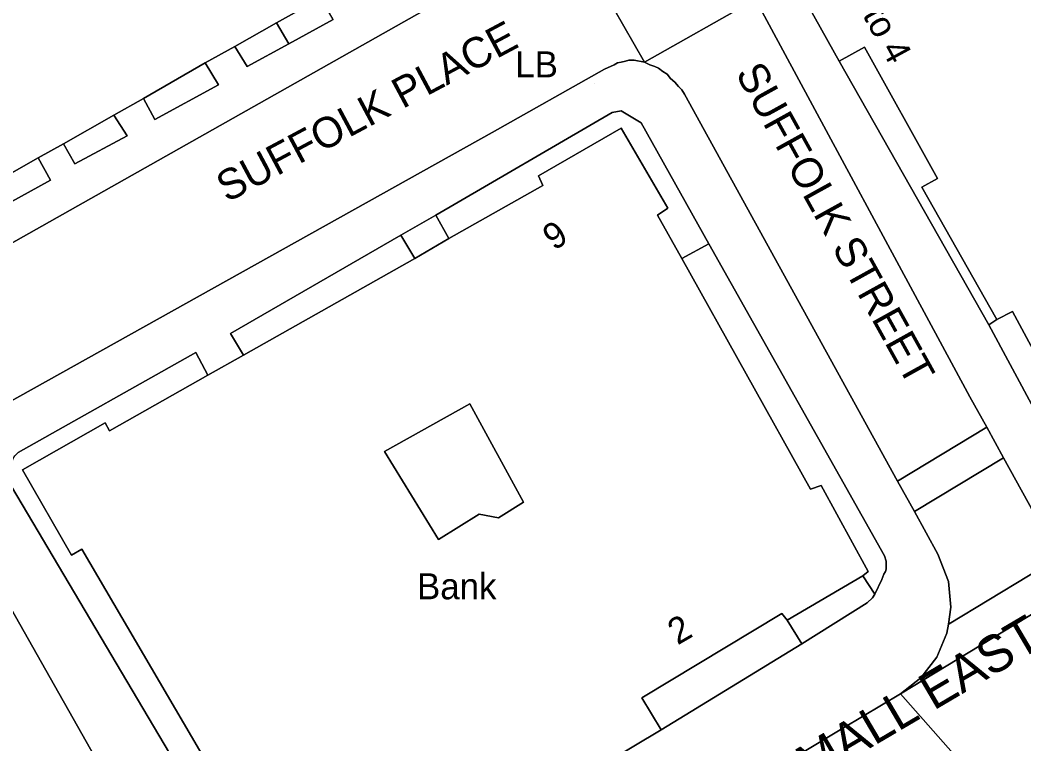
# Model space of a CAD drawing. Extents: x 529240 to 530363, y 179600 to 180767.
# Drawn here: x 529791.2 to 529848.9, y 180434.3 to 180475.9 of the extents above; entities that cross this region are included whole.
import ezdxf

# ---------------------------------------------------------------- set-up
doc = ezdxf.new("R2010")
doc.units = 0
for name, color, linetype in [('Building', 7, 'Continuous'), ('General surface', 7, 'Continuous'), ('Road Or Track', 7, 'Continuous'), ('Roadside', 7, 'Continuous'), ('Structure', 7, 'Continuous'), ('Unclassified', 7, 'Continuous')]:
    doc.layers.add(name, color=color, linetype=linetype)

msp = doc.modelspace()

# ---------------------------------------------------------------- linework, layer by layer
at = {"layer": 'Building'}
for points in [[(529786.55, 180464.75), (529792.25, 180468), (529793.7, 180468.8), (529796.6, 180470.45), (529798.3, 180471.4), (529801.85, 180473.45), (529803.55, 180474.4), (529805.95, 180475.75), (529808.5, 180477.2), (529810.3, 180478.25), (529818.45, 180482.85), (529815.15, 180488.6), (529810.7, 180486.15), (529807.1, 180484.1), (529806.15, 180485.75), (529804.1, 180484.5), (529802, 180483.3), (529799.8, 180487.05), (529800.55, 180487.5), (529798.55, 180490.95), (529797.45, 180492.85), (529794.4, 180498.1), (529771.3, 180485.1), (529783.65, 180463.1)], [(529847.35, 180458.7), (529843.05, 180466.3), (529843.95, 180466.8), (529839.75, 180474.35), (529838.3, 180473.55), (529846.9, 180458.4)], [(529812.15, 180451.1), (529817.05, 180453.85), (529820.15, 180448.2), (529818.7, 180447.3), (529817.6, 180447.5), (529815.25, 180446.05)], [(529835.3, 180441.4), (529836.15, 180440.05), (529839.9, 180442.4), (529840.2, 180442.7), (529840.35, 180442.9), (529839.65, 180443.95)]]:
    msp.add_lwpolyline(points, close=True, dxfattribs=at)
for points in [[(529851.4, 180488.55), (529847.75, 180486.4), (529844.7, 180491.5), (529840.9, 180497.9), (529829.65, 180492.1), (529836.55, 180479.75), (529835.2, 180479.1), (529838.3, 180473.55), (529839.75, 180474.35), (529843.95, 180466.8), (529843.05, 180466.3), (529847.35, 180458.7), (529848.25, 180459.15), (529852.1, 180452)], [(529835.2, 180479.1), (529838.3, 180473.55)], [(529805.95, 180475.75), (529808.5, 180477.2)], [(529803.55, 180474.4), (529805.95, 180475.75)], [(529801.85, 180473.45), (529803.55, 180474.4)], [(529847.35, 180458.7), (529843.05, 180466.3), (529843.95, 180466.8), (529839.75, 180474.35), (529838.3, 180473.55)], [(529798.3, 180471.4), (529801.85, 180473.45)], [(529796.6, 180470.45), (529798.3, 180471.4)], [(529793.7, 180468.8), (529796.6, 180470.45)], [(529820, 180430.3), (529828.05, 180435.1), (529826.95, 180436.95), (529835, 180441.8), (529835.3, 180441.4), (529839.65, 180443.95), (529839.95, 180444.2), (529837.25, 180449.15), (529836.65, 180448.95), (529829.25, 180462.2), (529827.85, 180464.7), (529828.45, 180465.1), (529825.75, 180469.7), (529821, 180466.95), (529821.25, 180466.4), (529815.85, 180463.35), (529813.9, 180462.2), (529804.05, 180456.65), (529802, 180455.5), (529796.35, 180452.3), (529796.1, 180452.75), (529791.35, 180450.05), (529794.15, 180445.15), (529794.75, 180445.5), (529804.15, 180429.45)], [(529815.85, 180463.35), (529821.25, 180466.4), (529821, 180466.95), (529825.75, 180469.7), (529828.45, 180465.1), (529827.85, 180464.7), (529829.25, 180462.2)], [(529792.25, 180468), (529793.7, 180468.8)], [(529786.55, 180464.75), (529792.25, 180468)], [(529847.35, 180458.7), (529848.25, 180459.15), (529852.1, 180452), (529867.28, 180461.19), (529874.9, 180465.8)], [(529813.9, 180462.2), (529815.85, 180463.35)], [(529804.05, 180456.65), (529813.9, 180462.2)], [(529829.25, 180462.2), (529836.65, 180448.95), (529837.25, 180449.15), (529839.95, 180444.2), (529839.65, 180443.95)], [(529802, 180455.5), (529804.05, 180456.65)], [(529820, 180430.3), (529819, 180432.05), (529810.85, 180427.15), (529811.1, 180426.65), (529806.65, 180423.95), (529803.55, 180429.05), (529804.15, 180429.45), (529794.75, 180445.5), (529794.15, 180445.15), (529791.35, 180450.05), (529796.1, 180452.75), (529796.35, 180452.3), (529802, 180455.5)], [(529812.15, 180451.1), (529815.25, 180446.05), (529817.6, 180447.5), (529818.7, 180447.3), (529820.15, 180448.2), (529817.05, 180453.85), (529812.15, 180451.1)], [(529839.65, 180443.95), (529835.3, 180441.4)], [(529839.65, 180443.95), (529840.35, 180442.9)], [(529835.3, 180441.4), (529835, 180441.8), (529826.95, 180436.95), (529828.05, 180435.1)], [(529828.05, 180435.1), (529820, 180430.3)]]:
    msp.add_lwpolyline(points, dxfattribs=at)
at = {"layer": 'General surface'}
for points in [[(529808.5, 180477.2), (529805.95, 180475.75), (529806.65, 180474.55), (529809.2, 180475.95)], [(529806.65, 180474.55), (529805.95, 180475.75), (529803.55, 180474.4), (529804.25, 180473.25)], [(529798.3, 180471.4), (529798.95, 180470.2), (529802.6, 180472.2), (529801.85, 180473.45)], [(529796.6, 180470.45), (529793.7, 180468.8), (529794.35, 180467.65), (529797.35, 180469.25)], [(529815.85, 180463.35), (529821.25, 180466.4), (529821, 180466.95), (529825.75, 180469.7), (529828.45, 180465.1), (529827.85, 180464.7), (529829.25, 180462.2), (529830.8, 180463.05), (529826.9, 180470), (529825.75, 180470.7), (529825.25, 180470.6), (529815.1, 180464.7)], [(529786.55, 180464.75), (529787.2, 180463.55), (529792.95, 180466.7), (529792.25, 180468)], [(529846.9, 180458.4), (529850.85, 180451.05), (529850.95, 180450.95), (529851.05, 180450.8), (529851.2, 180450.7), (529851.35, 180450.65), (529851.55, 180450.55), (529851.95, 180450.45), (529852.75, 180450.35), (529868.19, 180459.62), (529875.9, 180464.25), (529874.9, 180465.8), (529867.28, 180461.19), (529852.1, 180452), (529848.25, 180459.15), (529847.35, 180458.7)], [(529815.85, 180463.35), (529815.1, 180464.7), (529813.1, 180463.55), (529813.9, 180462.2)], [(529803.3, 180457.9), (529804.05, 180456.65), (529813.9, 180462.2), (529813.1, 180463.55)], [(529829.25, 180462.2), (529836.65, 180448.95), (529837.25, 180449.15), (529839.95, 180444.2), (529839.65, 180443.95), (529840.35, 180442.9), (529840.75, 180443.75), (529840.85, 180444.05), (529840.95, 180444.2), (529841, 180444.35), (529841, 180444.8), (529840.9, 180445.1), (529830.8, 180463.05)], [(529812.15, 180451.1), (529815.25, 180446.05), (529817.6, 180447.5), (529818.7, 180447.3), (529820.15, 180448.2), (529817.05, 180453.85)], [(529835.3, 180441.4), (529835, 180441.8), (529826.95, 180436.95), (529828.05, 180435.1), (529836.15, 180440.05)]]:
    msp.add_lwpolyline(points, close=True, dxfattribs=at)
msp.add_lwpolyline([(529790.7, 180449.1), (529805.8, 180423.6), (529805.95, 180423.45), (529806.5, 180423), (529806.6, 180422.95), (529806.7, 180422.85), (529807, 180422.7), (529807.25, 180422.7), (529807.45, 180422.8), (529820, 180430.3), (529819, 180432.05), (529810.85, 180427.15), (529811.1, 180426.65), (529806.65, 180423.95), (529803.55, 180429.05), (529804.15, 180429.45), (529794.75, 180445.5), (529794.15, 180445.15), (529791.35, 180450.05), (529796.1, 180452.75), (529796.35, 180452.3), (529802, 180455.5), (529801.3, 180456.8), (529791.1, 180451.05)], dxfattribs=at)
at = {"layer": 'Road Or Track'}
for points in [[(529827.1, 180473.5), (529833.48, 180477.11), (529828.83, 180485.42), (529822.35, 180481.8)], [(529827.1, 180473.5), (529827.4, 180473.35), (529827.7, 180473.25), (529827.9, 180473.15), (529828.15, 180472.95), (529828.4, 180472.8), (529828.6, 180472.55), (529828.85, 180472.35), (529829.05, 180472.1), (529829.25, 180471.9), (529829.4, 180471.65), (529841.65, 180449.4), (529846.78, 180452.5), (529845.81, 180454.25), (529833.48, 180477.11)], [(529847.74, 180450.75), (529846.78, 180452.5), (529841.65, 180449.4), (529842.62, 180447.65)], [(529847.74, 180450.75), (529842.62, 180447.65), (529843.96, 180445.21), (529844.57, 180443.63), (529844.71, 180442.15), (529844.57, 180441.18), (529844.61, 180441.2), (529851.45, 180445.33), (529851.1, 180445.58), (529850.59, 180445.95), (529849.86, 180446.9)], [(529841.82, 180437.17), (529855.04, 180445.19), (529853.89, 180444.86), (529852.7, 180444.88), (529851.56, 180445.25), (529851.45, 180445.33), (529844.61, 180441.2), (529844.57, 180441.18), (529844.49, 180440.67), (529843.9, 180439.29), (529842.99, 180438.1)], [(529855.04, 180445.19), (529841.82, 180437.17), (529846.15, 180432.27), (529846.48, 180432.34), (529846.74, 180432.2), (529846.85, 180431.64), (529852.12, 180431.04), (529853.55, 180433.47), (529856.1, 180436.61), (529858.54, 180438.84)], [(529813.74, 180420.91), (529819.63, 180415.23), (529819.86, 180415.75), (529839.31, 180427.98), (529841.93, 180429.63), (529846.13, 180432.27), (529846.15, 180432.27), (529841.82, 180437.17), (529838.54, 180435.21), (529835.89, 180433.62), (529819.89, 180424.05)]]:
    msp.add_lwpolyline(points, close=True, dxfattribs=at)
for points in [[(529821, 180480.2), (529784.7, 180459.7), (529783.31, 180458.62), (529782.36, 180458.26), (529782.17, 180458.23), (529785.79, 180450.85), (529786.04, 180451.39), (529786.72, 180452), (529788.7, 180452.9), (529818.35, 180469.45), (529824.8, 180473.1), (529825.35, 180473.35), (529825.55, 180473.45), (529825.75, 180473.5), (529826, 180473.55), (529826.2, 180473.6), (529826.5, 180473.6), (529827.1, 180473.5), (529822.35, 180481.8)], [(529822.35, 180481.8), (529822.2, 180481.6), (529822.1, 180481.4), (529821.9, 180481.1), (529821.7, 180480.75), (529821.6, 180480.6), (529821.4, 180480.45), (529821.2, 180480.35), (529821, 180480.2), (529784.7, 180459.7)], [(529845.81, 180454.25), (529833.48, 180477.11)], [(529827.1, 180473.5), (529826.5, 180473.6), (529826.2, 180473.6), (529826, 180473.55), (529825.75, 180473.5), (529825.55, 180473.45), (529825.35, 180473.35), (529824.8, 180473.1), (529818.35, 180469.45), (529788.7, 180452.9)], [(529841.65, 180449.4), (529829.4, 180471.65), (529829.25, 180471.9), (529829.05, 180472.1), (529828.85, 180472.35), (529828.6, 180472.55), (529828.4, 180472.8), (529828.15, 180472.95), (529827.9, 180473.15), (529827.7, 180473.25), (529827.4, 180473.35), (529827.1, 180473.5)], [(529846.78, 180452.5), (529845.81, 180454.25)], [(529841.65, 180449.4), (529846.78, 180452.5)], [(529847.74, 180450.75), (529846.78, 180452.5)], [(529785.79, 180450.85), (529785.84, 180450.07), (529786.2, 180449.5), (529787.2, 180448.25), (529787.2, 180448.15), (529787.85, 180447.05), (529799.57, 180426.36), (529802.21, 180421.75), (529802.43, 180421.45), (529803.1, 180420.55), (529803.21, 180420.46), (529804.27, 180419.62)], [(529842.62, 180447.65), (529847.74, 180450.75)], [(529851.45, 180445.33), (529851.1, 180445.58), (529850.59, 180445.95), (529849.86, 180446.9), (529847.74, 180450.75)], [(529841.65, 180449.4), (529842.62, 180447.65)], [(529842.62, 180447.65), (529843.96, 180445.21), (529844.57, 180443.63), (529844.71, 180442.15), (529844.57, 180441.18)], [(529791.11, 180425.75), (529791.69, 180425.65), (529793.41, 180422.93), (529797.23, 180416.06), (529798.25, 180414.59), (529804.27, 180419.62), (529803.21, 180420.46), (529803.1, 180420.55), (529802.43, 180421.45), (529802.21, 180421.75), (529799.57, 180426.36), (529787.85, 180447.05)], [(529841.82, 180437.17), (529855.04, 180445.19)], [(529844.57, 180441.18), (529844.61, 180441.2), (529851.45, 180445.33)], [(529844.57, 180441.18), (529844.49, 180440.67), (529843.9, 180439.29), (529842.99, 180438.1), (529841.82, 180437.17)], [(529813.74, 180420.91), (529819.89, 180424.05), (529835.89, 180433.62), (529838.54, 180435.21), (529841.82, 180437.17)]]:
    msp.add_lwpolyline(points, dxfattribs=at)
at = {"layer": 'Roadside'}
for points in [[(529808.6, 180521.15), (529810.1, 180518.5), (529814.75, 180510.05), (529820.65, 180500), (529828.83, 180485.42), (529833.48, 180477.11), (529845.81, 180454.25), (529846.78, 180452.5), (529847.74, 180450.75), (529849.86, 180446.9)], [(529850.85, 180451.05), (529846.9, 180458.4), (529838.3, 180473.55), (529835.2, 180479.1), (529828.35, 180491.4), (529824.7, 180497.95), (529825.9, 180498.8), (529825.05, 180500), (529822.6, 180503.7), (529821.75, 180503.2), (529818.1, 180509.25), (529818.2, 180509.3), (529816.05, 180513.3), (529817.1, 180513.9), (529816.35, 180515.4), (529815.15, 180514.65), (529813.15, 180518.2), (529814.3, 180518.85), (529813.5, 180520.4)], [(529763.1, 180490.7), (529780.25, 180460.2), (529781.22, 180458.32), (529781.96, 180458.2), (529782.17, 180458.23), (529782.36, 180458.26), (529783.31, 180458.62), (529784.7, 180459.7), (529821, 180480.2)], [(529809.2, 180475.95), (529806.65, 180474.55), (529804.25, 180473.25), (529803.55, 180474.4), (529801.85, 180473.45), (529802.6, 180472.2), (529798.95, 180470.2), (529798.3, 180471.4), (529796.6, 180470.45), (529797.35, 180469.25), (529794.35, 180467.65), (529793.7, 180468.8), (529792.25, 180468), (529792.95, 180466.7), (529787.2, 180463.55), (529786.55, 180464.75), (529783.65, 180463.1), (529771.3, 180485.1)], [(529835.89, 180433.62), (529838.54, 180435.21), (529841.82, 180437.17), (529842.99, 180438.1), (529843.9, 180439.29), (529844.49, 180440.67), (529844.57, 180441.18), (529844.71, 180442.15), (529844.57, 180443.63), (529843.96, 180445.21), (529842.62, 180447.65), (529841.65, 180449.4), (529829.4, 180471.65), (529829.25, 180471.9), (529829.05, 180472.1), (529828.85, 180472.35), (529828.6, 180472.55), (529828.4, 180472.8), (529828.15, 180472.95), (529827.9, 180473.15), (529827.7, 180473.25), (529827.4, 180473.35), (529827.1, 180473.5), (529826.5, 180473.6), (529826.2, 180473.6), (529826, 180473.55), (529825.75, 180473.5), (529825.55, 180473.45), (529825.35, 180473.35), (529824.8, 180473.1), (529818.35, 180469.45), (529788.7, 180452.9)], [(529791.1, 180451.05), (529801.3, 180456.8), (529802, 180455.5), (529804.05, 180456.65), (529803.3, 180457.9), (529813.1, 180463.55), (529815.1, 180464.7), (529825.25, 180470.6), (529825.75, 180470.7), (529826.9, 180470), (529830.8, 180463.05), (529840.9, 180445.1), (529841, 180444.8), (529841, 180444.35), (529840.95, 180444.2), (529840.85, 180444.05), (529840.75, 180443.75), (529840.35, 180442.9), (529840.2, 180442.7), (529839.9, 180442.4), (529836.15, 180440.05), (529828.05, 180435.1), (529820, 180430.3)], [(529805.8, 180423.6), (529790.7, 180449.1)], [(529787.85, 180447.05), (529799.57, 180426.36)]]:
    msp.add_lwpolyline(points, dxfattribs=at)
at = {"layer": 'Structure'}
msp.add_line((529824.2, 180472.25), (529824.2, 180472.25), dxfattribs=at)
at = {"layer": 'Unclassified'}
for points in [[(529827.1, 180473.5), (529822.35, 180481.8)], [(529806.65, 180474.55), (529809.2, 180475.95), (529808.5, 180477.2)], [(529827.1, 180473.5), (529833.48, 180477.11)], [(529806.65, 180474.55), (529805.95, 180475.75)], [(529803.55, 180474.4), (529804.25, 180473.25), (529806.65, 180474.55)], [(529798.3, 180471.4), (529798.95, 180470.2), (529802.6, 180472.2), (529801.85, 180473.45)], [(529838.3, 180473.55), (529846.9, 180458.4)], [(529793.7, 180468.8), (529794.35, 180467.65), (529797.35, 180469.25), (529796.6, 180470.45)], [(529815.1, 180464.7), (529825.25, 180470.6), (529825.75, 180470.7), (529826.9, 180470), (529830.8, 180463.05)], [(529786.55, 180464.75), (529787.2, 180463.55), (529792.95, 180466.7), (529792.25, 180468)], [(529874.9, 180465.8), (529875.9, 180464.25), (529868.19, 180459.62), (529852.75, 180450.35), (529851.95, 180450.45), (529851.55, 180450.55), (529851.35, 180450.65), (529851.2, 180450.7), (529851.05, 180450.8), (529850.95, 180450.95), (529850.85, 180451.05), (529846.9, 180458.4)], [(529813.1, 180463.55), (529815.1, 180464.7)], [(529815.1, 180464.7), (529815.85, 180463.35)], [(529803.3, 180457.9), (529813.1, 180463.55)], [(529813.1, 180463.55), (529813.9, 180462.2)], [(529830.8, 180463.05), (529829.25, 180462.2)], [(529830.8, 180463.05), (529840.9, 180445.1), (529841, 180444.8), (529841, 180444.35), (529840.95, 180444.2), (529840.85, 180444.05), (529840.75, 180443.75), (529840.35, 180442.9)], [(529846.9, 180458.4), (529847.35, 180458.7)], [(529804.05, 180456.65), (529803.3, 180457.9)], [(529820, 180430.3), (529807.45, 180422.8), (529807.25, 180422.7), (529807, 180422.7), (529806.7, 180422.85), (529806.6, 180422.95), (529806.5, 180423), (529805.95, 180423.45), (529805.8, 180423.6), (529790.7, 180449.1), (529790.65, 180449.35), (529790.65, 180450.2), (529790.7, 180450.4), (529790.8, 180450.7), (529790.9, 180450.85), (529791.1, 180451.05), (529801.3, 180456.8)], [(529801.3, 180456.8), (529802, 180455.5)], [(529840.35, 180442.9), (529840.2, 180442.7), (529839.9, 180442.4), (529836.15, 180440.05)], [(529835.3, 180441.4), (529836.15, 180440.05)], [(529836.15, 180440.05), (529828.05, 180435.1)], [(529846.15, 180432.27), (529841.82, 180437.17)]]:
    msp.add_lwpolyline(points, dxfattribs=at)

# ---------------------------------------------------------------- texts
at = {"layer": 'Road Or Track'}
for s, height, rotation, p in [('SUFFOLK PLACE', 1.75, 28.1, (529803.1, 180465.4)), ('SUFFOLK STREET', 1.75, 299, (529832.3, 180472.85)), ('PALL MALL EAST', 2.125, 30.5, (529829.97, 180428.09))]:
    msp.add_text(s, height=height, rotation=rotation, dxfattribs=at).set_placement(p)
at = {"layer": 'Structure'}
msp.add_text('LB', height=1.5, dxfattribs=at).set_placement((529819.67, 180472.62))
at = {"layer": 'Unclassified'}
for s, rotation, p in [('1 to 4', 298.5, (529838.81, 180477.69)), ('6', 213.6, (529822, 180464.49)), ('2', 30, (529829, 180439.95))]:
    msp.add_text(s, height=1.5, rotation=rotation, dxfattribs=at).set_placement(p)
msp.add_text('Bank', height=1.5, dxfattribs=at).set_placement((529814.02, 180442.61))

doc.saveas('drawing.dxf')
